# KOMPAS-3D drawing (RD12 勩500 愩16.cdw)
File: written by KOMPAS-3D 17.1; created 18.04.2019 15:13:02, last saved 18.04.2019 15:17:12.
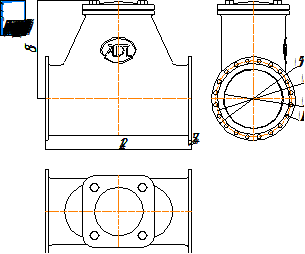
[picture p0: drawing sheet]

Sheet 1: A4, portrait

Title block, sheet 1: name: RD12 Ду500 Ру16; material: Внимание! Данный продукт является объектом авторского права ООО «Торговый Дом АДЛ». / Запрещается изменение, копирование, распространение / (в том числе путем копирования на другие сайты и ресурсы в Интернете) / или любое иное использование информации и объектов без предварительного / согласия правообладателя (ООО «Торговый Дом АДЛ»).; mass: 3416,1; sheets: 1; organisation: ООО "Торговый дом АДЛ"; sheet format: A4

Views: Вид 1, Проекционный вид 2, Проекционный вид 3
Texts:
  user
Dimensions and other numbers on the sheet: 27,5; 4; 1242; 835; 650; 715; 500; 35; 20 отв.; 1:1; 1; 3416,1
